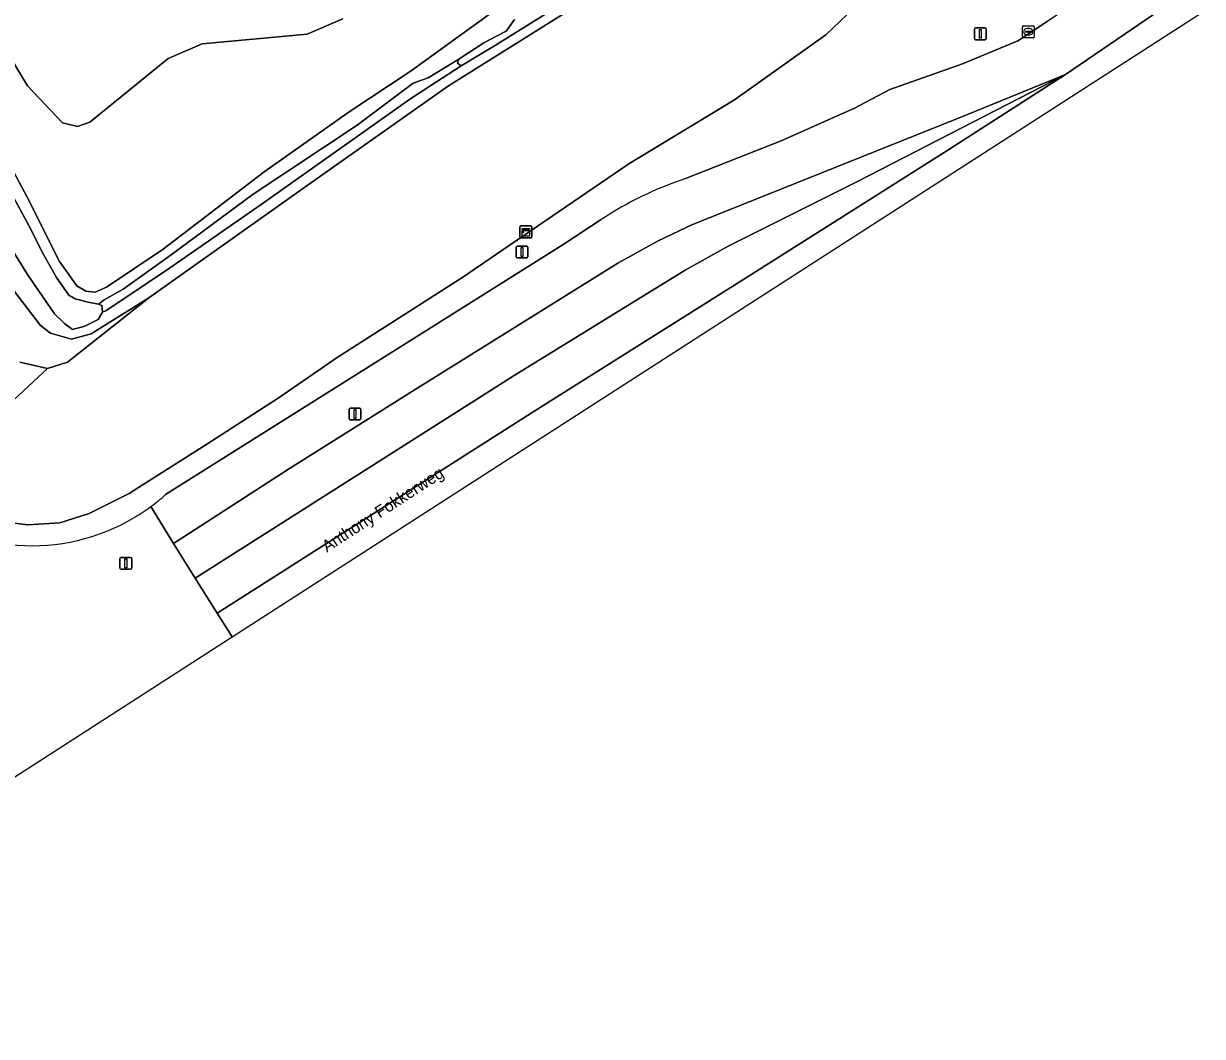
# Model space of a CAD drawing. Extents: x 155209 to 156748, y 385356 to 388487.
# Drawn here: x 156378.1 to 156477.1, y 385537.4 to 385622.5 of the extents above; entities that cross this region are included whole.
import ezdxf

# ---------------------------------------------------------------- set-up
doc = ezdxf.new("R2010")
doc.units = 0
for name, color, linetype in [('IMGEO_Berm_groen', 7, 'Continuous'), ('IMGEO_Grasland_overig', 7, 'Continuous'), ('IMGEO_Groenvoorziening', 7, 'Continuous'), ('IMGEO_Kast', 7, 'Continuous'), ('IMGEO_Kolk', 7, 'Continuous'), ('IMGEO_Lichtmast', 7, 'Continuous'), ('IMGEO_Oever', 7, 'Continuous'), ('IMGEO_Openbare_ruimte_label', 7, 'Continuous'), ('IMGEO_Rijbaan_regionaal_gesloten', 7, 'Continuous'), ('IMGEO_Struiken', 7, 'Continuous'), ('IMGEO_Verkeersregelinstallatiepaal', 7, 'Continuous'), ('IMGEO_Waterloop', 7, 'Continuous')]:
    doc.layers.add(name, color=color, linetype=linetype)

msp = doc.modelspace()

# ---------------------------------------------------------------- linework, layer by layer
at = {"layer": 'IMGEO_Berm_groen'}
for points in [[(156404.946, 385622.854), (156401.942, 385621.582), (156393.128, 385620.759), (156390.293, 385619.542), (156383.72, 385614.179), (156382.677, 385613.821), (156381.42, 385614.137), (156378.462, 385617.236), (156370.433, 385630.641)], [(156372.356, 385619.275), (156378.435, 385607.892), (156381.155, 385602.498), (156382.602, 385600.438), (156383.366, 385599.998), (156384.142, 385599.926), (156385.109, 385600.346), (156389.861, 385603.519), (156398.333, 385610.031), (156405.549, 385615.097), (156410.596, 385618.442), (156421.793, 385626.545)], [(156447.271, 385623.223), (156445.495, 385621.514), (156437.826, 385616.061), (156428.96, 385610.685), (156414.93, 385601.126), (156404.471, 385594.429), (156399.592, 385591.086), (156393.447, 385587.088), (156387.795, 385583.512), (156387.001, 385583.009), (156383.647, 385581.345), (156381.178, 385580.557), (156378.507, 385580.378), (156376.471, 385580.622)], [(156433.715, 385609.463), (156441.742, 385612.613), (156447.888, 385615.369), (156450.841, 385616.922), (156456.965, 385619.087), (156461.602, 385621.012), (156464.046, 385622.651)], [(156390.069, 385582.925), (156423.347, 385603.864), (156426.628, 385606.007)], [(156377.833, 385594.025), (156380.163, 385593.508), (156381.827, 385594.027), (156388.665, 385599.442), (156383.81, 385596.415), (156382.182, 385595.975), (156380.398, 385596.479), (156379.562, 385597.103), (156377.397, 385599.974)]]:
    msp.add_lwpolyline(points, dxfattribs=at)
for centre, radius, start, end in [((156443.608, 385580.182), 30.907, 108.66801, 123.32466), ((156378.825, 385595.473), 16.848, 230.87433, 300.91728), ((156378.607, 385595.744), 17.196, 306.44059, 311.80242), ((156378.996, 385595.224), 16.546, 300.85492, 306.42641)]:
    msp.add_arc(centre, radius, start, end, dxfattribs=at)
at = {"layer": 'IMGEO_Grasland_overig'}
msp.add_lwpolyline([(156369.992, 385584.071), (156380.163, 385593.508), (156377.833, 385594.025)], dxfattribs=at)
at = {"layer": 'IMGEO_Groenvoorziening'}
for points in [[(156427.264, 385625.693), (156413.818, 385617.24), (156401.74, 385608.727), (156388.665, 385599.442), (156381.827, 385594.027), (156380.163, 385593.508), (156369.992, 385584.071)], [(156376.471, 385580.622), (156378.507, 385580.378), (156381.178, 385580.557), (156383.647, 385581.345), (156387.001, 385583.009), (156387.795, 385583.512), (156393.447, 385587.088), (156399.592, 385591.086), (156404.471, 385594.429), (156414.93, 385601.126), (156428.96, 385610.685), (156437.826, 385616.061), (156445.495, 385621.514), (156447.271, 385623.223)]]:
    msp.add_lwpolyline(points, dxfattribs=at)
at = {"layer": 'IMGEO_Kast'}
for p, q in [((156419.808, 385604.555), (156419.808, 385605.396)), ((156419.808, 385605.396), (156419.808, 385604.555)), ((156419.883, 385605.48), (156420.724, 385605.48)), ((156420.724, 385605.48), (156419.883, 385605.48)), ((156420.808, 385605.405), (156420.808, 385604.564)), ((156420.808, 385604.564), (156420.808, 385605.405)), ((156420.733, 385604.48), (156419.892, 385604.48)), ((156419.892, 385604.48), (156420.733, 385604.48))]:
    msp.add_line(p, q, dxfattribs=at)
for points in [[(156420.003, 385605.27), (156420.603, 385605.27), (156420.603, 385605.185), (156420.003, 385605.185), (156420.003, 385605.27)], [(156420.003, 385605.095), (156420.603, 385605.095), (156420.603, 385604.606), (156420.003, 385604.606), (156420.003, 385605.095)]]:
    msp.add_lwpolyline(points, dxfattribs=at)
msp.add_circle((156420.087, 385604.944), 0.0377, dxfattribs=at)
for centre, start, end in [((156419.886, 385605.402), 92.4484, 184.28452), ((156419.886, 385605.402), 92.4484, 184.28452), ((156420.73, 385605.402), 2.4484, 94.28452), ((156420.73, 385605.402), 2.4484, 94.28452), ((156419.886, 385604.558), 182.4484, 274.28452), ((156419.886, 385604.558), 182.4484, 274.28452), ((156420.73, 385604.558), 272.4484, 4.28452), ((156420.73, 385604.558), 272.4484, 4.28452)]:
    msp.add_arc(centre, 0.0779, start, end, dxfattribs=at)
at = {"layer": 'IMGEO_Kolk'}
for p, q in [((156461.979, 385621.35), (156461.979, 385622.202)), ((156462.054, 385622.276), (156462.906, 385622.276)), ((156462.467, 385622.056), (156462.492, 385622.056)), ((156462.98, 385622.202), (156462.98, 385621.35)), ((156462.906, 385621.276), (156462.054, 385621.276)), ((156462.238, 385621.77), (156462.238, 385621.782)), ((156462.676, 385621.733), (156462.278, 385621.733)), ((156462.281, 385621.819), (156462.679, 385621.819)), ((156462.49, 385621.496), (156462.465, 385621.496)), ((156462.722, 385621.782), (156462.722, 385621.77))]:
    msp.add_line(p, q, dxfattribs=at)
for points in [[(156461.979, 385621.35), (156461.979, 385622.202)], [(156462.054, 385622.276), (156462.906, 385622.276)], [(156462.98, 385622.202), (156462.98, 385621.35)], [(156462.906, 385621.276), (156462.054, 385621.276)]]:
    msp.add_lwpolyline(points, dxfattribs=at)
for centre, radius, start, end in [((156462.056, 385622.2), 0.0765, 91.55205, 178.44795), ((156462.056, 385622.2), 0.0765, 91.55205, 178.44795), ((156462.904, 385622.2), 0.0765, 1.55205, 88.44795), ((156462.904, 385622.2), 0.0765, 1.55205, 88.44795), ((156462.056, 385621.352), 0.0765, 181.55205, 268.44795), ((156462.056, 385621.352), 0.0765, 181.55205, 268.44795), ((156462.278, 385621.779), 0.0403, 85.87752, 175.75265), ((156462.275, 385621.769), 0.0366, 178.93798, 274.71019), ((156462.679, 385621.776), 0.043, 264.86636, 352.45326), ((156462.683, 385621.781), 0.0386, 1.73085, 96.63898), ((156462.904, 385621.352), 0.0765, 271.55205, 358.44795), ((156462.904, 385621.352), 0.0765, 271.55205, 358.44795)]:
    msp.add_arc(centre, radius, start, end, dxfattribs=at)
for centre, major_axis, ratio, start_param, end_param in [((156462.466, 385621.776), (-0.387, 0.002), 0.722429, 4.712389, 7.853982), ((156462.491, 385621.776), (-0.39, 0.002), 0.717154, 1.570796, 4.712389)]:
    msp.add_ellipse(centre, major_axis=major_axis, ratio=ratio, start_param=start_param, end_param=end_param, dxfattribs=at)
at = {"layer": 'IMGEO_Lichtmast'}
for p, q in [((156457.948, 385621.203), (156457.948, 385622.003)), ((156457.948, 385622.003), (156457.948, 385621.203)), ((156458.048, 385622.103), (156458.838, 385622.103)), ((156458.838, 385622.103), (156458.048, 385622.103)), ((156458.938, 385622.003), (156458.938, 385621.203)), ((156458.938, 385621.203), (156458.938, 385622.003)), ((156458.838, 385621.103), (156458.048, 385621.103)), ((156458.048, 385621.103), (156458.838, 385621.103)), ((156419.485, 385602.885), (156419.485, 385603.685)), ((156419.485, 385603.685), (156419.485, 385602.885)), ((156419.585, 385603.785), (156420.375, 385603.785)), ((156420.375, 385603.785), (156419.585, 385603.785)), ((156420.475, 385603.685), (156420.475, 385602.885)), ((156420.475, 385602.885), (156420.475, 385603.685)), ((156420.375, 385602.785), (156419.585, 385602.785)), ((156419.585, 385602.785), (156420.375, 385602.785)), ((156405.465, 385589.287), (156405.465, 385590.087)), ((156405.465, 385590.087), (156405.465, 385589.287)), ((156405.565, 385590.187), (156406.355, 385590.187)), ((156406.355, 385590.187), (156405.565, 385590.187)), ((156406.455, 385590.087), (156406.455, 385589.287)), ((156406.455, 385589.287), (156406.455, 385590.087)), ((156406.355, 385589.187), (156405.565, 385589.187)), ((156405.565, 385589.187), (156406.355, 385589.187))]:
    msp.add_line(p, q, dxfattribs=at)
for points in [[(156458.368, 385621.978), (156458.518, 385621.978), (156458.518, 385621.228), (156458.368, 385621.228), (156458.368, 385621.978)], [(156419.905, 385603.66), (156420.055, 385603.66), (156420.055, 385602.91), (156419.905, 385602.91), (156419.905, 385603.66)], [(156405.885, 385590.062), (156406.035, 385590.062), (156406.035, 385589.312), (156405.885, 385589.312), (156405.885, 385590.062)]]:
    msp.add_lwpolyline(points, dxfattribs=at)
for centre, start, end in [((156458.048, 385622.003), 90, 180), ((156458.048, 385622.003), 90, 180), ((156458.838, 385622.003), 0, 90), ((156458.838, 385622.003), 360, 90), ((156458.048, 385621.203), 180, 270), ((156458.048, 385621.203), 180, 270), ((156458.838, 385621.203), 270, 0), ((156458.838, 385621.203), 270, 0), ((156419.585, 385603.685), 90, 180), ((156419.585, 385603.685), 90, 180), ((156420.375, 385603.685), 0, 90), ((156420.375, 385603.685), 360, 90), ((156419.585, 385602.885), 180, 270), ((156419.585, 385602.885), 180, 270), ((156420.375, 385602.885), 270, 0), ((156420.375, 385602.885), 270, 0), ((156405.565, 385590.087), 90, 180), ((156405.565, 385590.087), 90, 180), ((156405.565, 385589.287), 180, 270), ((156405.565, 385589.287), 180, 270), ((156406.355, 385590.087), 0, 90), ((156406.355, 385590.087), 360, 90), ((156406.355, 385589.287), 270, 0), ((156406.355, 385589.287), 270, 0)]:
    msp.add_arc(centre, 0.1, start, end, dxfattribs=at)
at = {"layer": 'IMGEO_Oever'}
for points in [[(156421.793, 385626.545), (156410.596, 385618.442), (156405.549, 385615.097), (156398.333, 385610.031), (156389.861, 385603.519), (156385.109, 385600.346), (156384.142, 385599.926), (156383.366, 385599.998), (156382.602, 385600.438), (156381.155, 385602.498), (156378.435, 385607.892), (156372.356, 385619.275)], [(156377.397, 385599.974), (156379.562, 385597.103), (156380.398, 385596.479), (156382.182, 385595.975), (156383.81, 385596.415), (156388.665, 385599.442), (156401.74, 385608.727), (156413.818, 385617.24), (156427.264, 385625.693)], [(156422.107, 385623.361), (156417.678, 385620.59), (156414.876, 385618.904), (156410.653, 385616.173), (156405.271, 385612.373), (156398.076, 385607.274), (156390.401, 385601.931), (156386.383, 385599.24), (156385.082, 385598.364), (156384.768, 385598.248), (156384.399, 385597.631), (156383.29, 385597.074), (156382.258, 385596.769), (156381.59, 385597.289), (156380.735, 385598.086), (156378.47, 385601.401), (156375.89, 385605.519)], [(156377.093, 385608.252), (156378.621, 385605.45), (156379.807, 385603.066), (156380.907, 385601.143), (156381.943, 385599.65), (156382.464, 385599.358), (156383.577, 385599.078), (156384.434, 385598.91), (156384.902, 385599.258), (156386.497, 385600.165), (156390.546, 385603.052), (156397.427, 385608.151), (156406.136, 385613.939), (156410.848, 385617.474), (156412.11, 385617.909), (156414.692, 385619.478), (156416.776, 385620.858), (156417.883, 385621.433), (156418.661, 385621.815), (156419.338, 385622.814)]]:
    msp.add_lwpolyline(points, dxfattribs=at)
at = {"layer": 'IMGEO_Rijbaan_regionaal_gesloten'}
for points in [[(156465.604, 385618.181), (156476.067, 385625.34), (156474.024, 385629.181), (156464.046, 385622.651), (156461.602, 385621.012), (156456.965, 385619.087), (156450.841, 385616.922), (156447.888, 385615.369), (156441.742, 385612.613), (156433.715, 385609.463)], [(156388.821, 385581.91), (156390.741, 385578.808), (156400.477, 385585.106), (156410.798, 385591.611), (156428.016, 385602.356), (156431.414, 385604.213), (156434.278, 385605.582), (156456.767, 385614.588), (156465.604, 385618.181)], [(156426.628, 385606.007), (156423.347, 385603.864), (156390.069, 385582.925)], [(156343.555, 385537.434), (156395.645, 385570.975), (156394.398, 385572.967), (156392.557, 385575.906), (156390.741, 385578.808), (156388.821, 385581.91)]]:
    msp.add_lwpolyline(points, dxfattribs=at)
for points in [[(156395.645, 385570.975), (156477.09, 385623.418), (156476.067, 385625.34), (156465.604, 385618.181), (156455.421, 385611.654), (156438.218, 385600.76), (156421.059, 385589.944), (156394.398, 385572.967)], [(156433.672, 385601.759), (156437.275, 385603.78), (156448.138, 385609.208), (156465.604, 385618.181), (156456.767, 385614.588), (156434.278, 385605.582), (156431.414, 385604.213), (156428.016, 385602.356), (156410.798, 385591.611), (156400.477, 385585.106), (156390.741, 385578.808), (156392.557, 385575.906), (156419.309, 385592.921)], [(156438.218, 385600.76), (156455.421, 385611.654), (156465.604, 385618.181), (156448.138, 385609.208), (156437.275, 385603.78), (156433.672, 385601.759), (156419.309, 385592.921), (156392.557, 385575.906), (156394.398, 385572.967), (156421.059, 385589.944)]]:
    msp.add_lwpolyline(points, close=True, dxfattribs=at)
for centre, radius, start, end in [((156443.608, 385580.182), 30.907, 108.66801, 123.32466), ((156378.825, 385595.473), 16.848, 230.87433, 300.91728), ((156378.607, 385595.744), 17.196, 306.44059, 311.80242), ((156378.996, 385595.224), 16.546, 300.85492, 306.42641)]:
    msp.add_arc(centre, radius, start, end, dxfattribs=at)
at = {"layer": 'IMGEO_Struiken'}
msp.add_lwpolyline([(156370.433, 385630.641), (156378.462, 385617.236), (156381.42, 385614.137), (156382.677, 385613.821), (156383.72, 385614.179), (156390.293, 385619.542), (156393.128, 385620.759), (156401.942, 385621.582), (156404.946, 385622.854)], dxfattribs=at)
at = {"layer": 'IMGEO_Verkeersregelinstallatiepaal'}
for p, q in [((156386.23, 385576.75), (156386.23, 385577.55)), ((156386.23, 385577.55), (156386.23, 385576.75)), ((156386.33, 385577.65), (156387.12, 385577.65)), ((156387.12, 385577.65), (156386.33, 385577.65)), ((156387.22, 385577.55), (156387.22, 385576.75)), ((156387.22, 385576.75), (156387.22, 385577.55)), ((156387.12, 385576.65), (156386.33, 385576.65)), ((156386.33, 385576.65), (156387.12, 385576.65))]:
    msp.add_line(p, q, dxfattribs=at)
msp.add_lwpolyline([(156386.65, 385577.525), (156386.8, 385577.525), (156386.8, 385576.775), (156386.65, 385576.775), (156386.65, 385577.525)], dxfattribs=at)
for centre, start, end in [((156386.33, 385577.55), 90, 180), ((156386.33, 385577.55), 90, 180), ((156387.12, 385577.55), 0, 90), ((156387.12, 385577.55), 360, 90), ((156386.33, 385576.75), 180, 270), ((156386.33, 385576.75), 180, 270), ((156387.12, 385576.75), 270, 0), ((156387.12, 385576.75), 270, 0)]:
    msp.add_arc(centre, 0.1, start, end, dxfattribs=at)
at = {"layer": 'IMGEO_Waterloop'}
for points in [[(156419.338, 385622.814), (156418.661, 385621.815), (156417.883, 385621.433), (156416.776, 385620.858), (156414.692, 385619.478), (156414.553, 385619.148), (156414.876, 385618.904), (156417.678, 385620.59), (156422.107, 385623.361)], [(156375.89, 385605.519), (156378.47, 385601.401), (156380.735, 385598.086), (156381.59, 385597.289), (156382.258, 385596.769), (156383.29, 385597.074), (156384.399, 385597.631), (156384.768, 385598.248), (156384.727, 385598.784), (156384.434, 385598.91), (156383.577, 385599.078), (156382.464, 385599.358), (156381.943, 385599.65), (156380.907, 385601.143), (156379.807, 385603.066), (156378.621, 385605.45), (156377.093, 385608.252)]]:
    msp.add_lwpolyline(points, dxfattribs=at)
msp.add_lwpolyline([(156414.876, 385618.904), (156414.553, 385619.148), (156414.692, 385619.478), (156412.11, 385617.909), (156410.848, 385617.474), (156406.136, 385613.939), (156397.427, 385608.151), (156390.546, 385603.052), (156386.497, 385600.165), (156384.902, 385599.258), (156384.434, 385598.91), (156384.727, 385598.784), (156384.768, 385598.248), (156385.082, 385598.364), (156386.383, 385599.24), (156390.401, 385601.931), (156398.076, 385607.274), (156405.271, 385612.373), (156410.653, 385616.173)], close=True, dxfattribs=at)

# ---------------------------------------------------------------- texts
at = {"layer": 'IMGEO_Openbare_ruimte_label'}
msp.add_text('Anthony Fokkerweg', height=1, rotation=32.95901, dxfattribs=at).set_placement((156403.605, 385578.042))

doc.saveas('drawing.dxf')
